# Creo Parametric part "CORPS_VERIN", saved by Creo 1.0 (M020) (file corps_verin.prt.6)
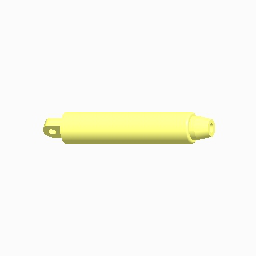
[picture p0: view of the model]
Units: millimeter Newton Second (mmNs); MM, TONNE, SECS
Materials in the file: FE20

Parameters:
  PTC_MATERIAL_NAME = "FE20"

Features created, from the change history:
  datum axis "A_1"
  datum plane "DTM1"
  datum axis "A_2"
  datum plane "DTM2"
  datum point "PNT0"

Other named items: CORPS_VERIN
